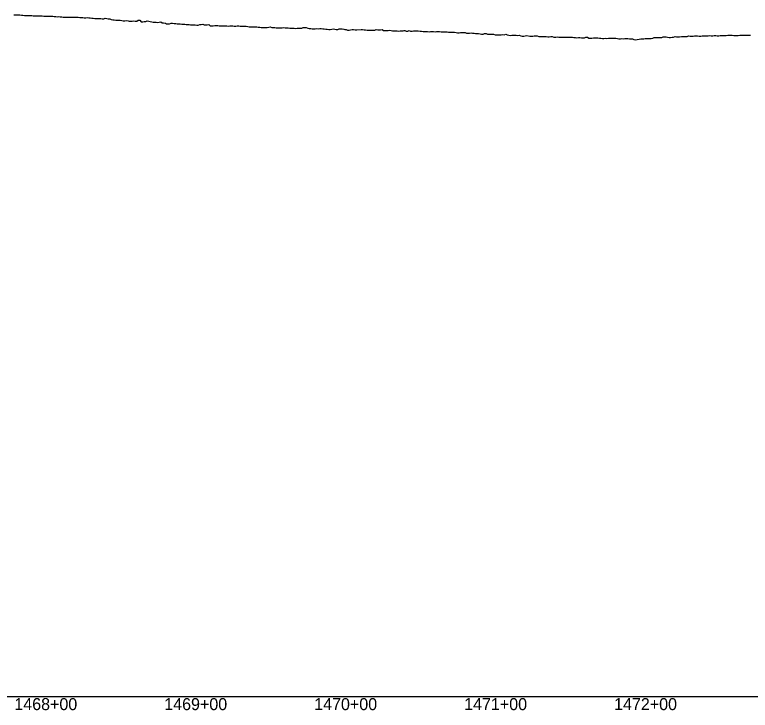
# Model space of a CAD drawing. Extents: x -3793 to 50787, y -1075 to 6138.
# Drawn here: x 34158.7 to 34649.2, y 990.9 to 1455 of the extents above; entities that cross this region are included whole.
import ezdxf

# ---------------------------------------------------------------- set-up
doc = ezdxf.new("R2010")
doc.units = 0
for name, color, linetype in [('RD_DDB_Profile_EX', 7, 'Continuous'), ('RD_DDB_StaTX', 7, 'Continuous'), ('RD_GPK_Profile_Cell', 7, 'Continuous')]:
    doc.layers.add(name, color=color, linetype=linetype)

msp = doc.modelspace()

# ---------------------------------------------------------------- linework, layer by layer
at = {"layer": 'RD_DDB_Profile_EX'}
for points in [[(34158.089552, 1454.92053), (34159.07989, 1454.87333), (34160.079882, 1454.911675), (34161.079874, 1454.95004), (34162.078945, 1454.81324), (34163.079056, 1454.55282), (34164.07905, 1454.597655), (34165.079045, 1454.508055), (34166.07701, 1454.4104), (34167.07712, 1454.41613), (34168.077118, 1454.454855), (34169.07621, 1454.446225), (34170.07621, 1454.42426), (34171.076209, 1454.28498), (34172.075414, 1454.2824), (34173.075415, 1454.248315), (34174.075417, 1454.18207), (34175.075419, 1454.271205), (34176.074625, 1454.263505), (34177.074628, 1454.1239), (34178.074631, 1454.073745), (34179.073733, 1454.015755), (34180.073842, 1453.991835), (34181.073848, 1454.03131), (34182.073853, 1454.015625), (34183.072958, 1454.057815), (34184.072965, 1454.01277), (34185.072172, 1453.82037), (34186.071277, 1453.68226), (34187.069473, 1453.630875), (34188.068576, 1453.66362), (34189.067772, 1453.61553), (34190.066873, 1453.42149), (34191.065974, 1453.4094), (34192.065076, 1453.40199), (34193.063337, 1453.350565), (34194.062435, 1453.351585), (34195.061533, 1453.336385), (34196.060631, 1453.387405), (34197.059729, 1453.388255), (34198.057964, 1453.28608), (34199.057059, 1453.34368), (34200.056153, 1453.31921), (34201.055247, 1453.309455), (34202.05441, 1453.160245), (34203.052614, 1453.107965), (34204.051767, 1452.976885), (34205.050916, 1452.9085), (34206.050001, 1452.890745), (34207.039704, 1452.982505), (34208.038828, 1452.938425), (34209.036954, 1452.790795), (34210.036068, 1452.6879), (34211.034692, 1452.53743), (34212.033816, 1452.436775), (34213.032889, 1452.47676), (34214.03101, 1452.32923), (34215.030121, 1452.322025), (34216.029229, 1452.31131), (34217.028333, 1452.260425), (34218.027433, 1452.305865), (34219.025511, 1452.5908), (34220.024601, 1452.37966), (34221.023657, 1452.28345), (34222.022741, 1452.283985), (34223.021822, 1451.74514), (34224.020898, 1451.54417), (34225.018928, 1451.487115), (34226.017993, 1451.382805), (34227.017055, 1451.330205), (34228.016098, 1451.372575), (34229.015153, 1451.22082), (34230.01314, 1451.065995), (34231.012184, 1450.962795), (34232.011224, 1450.95871), (34233.010261, 1451.0547), (34234.257573, 1450.850485), (34235.010263, 1450.557785), (34236.011246, 1450.612415), (34237.012232, 1450.615675), (34238.01321, 1450.81695), (34239.014186, 1450.72107), (34240.015169, 1450.676855), (34241.017106, 1451.227365), (34242.018071, 1451.281225), (34243.009219, 1450.298155), (34244.010195, 1450.297345), (34245.011187, 1450.35047), (34246.011189, 1450.40214), (34247.010219, 1450.830285), (34248.009262, 1450.63213), (34249.008284, 1450.48081), (34250.008286, 1450.2841), (34251.007316, 1450.07453), (34252.00633, 1450.023285), (34253.00534, 1449.874915), (34254.004354, 1449.771295), (34255.003355, 1449.965175), (34256.003357, 1450.16358), (34257.002358, 1449.560635), (34258.001351, 1449.505855)], [(34258.001351, 1449.505855), (34259.173674, 1449.40457), (34260.001167, 1448.953355), (34261.001281, 1448.95374), (34262.002489, 1448.958175), (34263.003692, 1449.26047), (34264.004891, 1449.313685), (34265.006097, 1449.118695), (34266.007289, 1449.07071), (34267.007416, 1448.969135), (34268.008606, 1448.873715), (34269.009809, 1448.827135), (34270.010993, 1448.728705), (34271.012194, 1448.63292), (34272.013371, 1448.53726), (34273.064954, 1448.4941), (34274.039694, 1448.40109), (34275.009409, 1448.356885), (34275.974137, 1448.1683), (34277.018247, 1448.11147), (34278.018361, 1448.15867), (34279.019558, 1448.11418), (34280.020717, 1448.068055), (34281.021912, 1448.02205), (34282.023106, 1448.36274), (34283.024258, 1448.361915), (34284.024414, 1448.55216), (34285.025563, 1448.26937), (34286.026756, 1448.17486), (34287.027898, 1448.1781), (34288.029088, 1448.3719), (34289.029202, 1447.46528), (34290.030392, 1447.562555), (34291.031526, 1447.616815), (34292.032714, 1447.7632), (34293.033842, 1447.81157), (34294.035028, 1447.671315), (34295.035141, 1447.577315), (34296.036327, 1447.53467), (34297.037447, 1447.476525), (34298.038631, 1447.48058), (34299.039744, 1447.49094), (34300.040926, 1447.488435), (34301.041039, 1447.388645), (34302.04222, 1447.43573), (34303.043326, 1447.49647), (34304.043515, 1447.45412), (34305.044618, 1447.25807), (34306.044809, 1447.204895), (34307.04591, 1447.486065), (34308.046104, 1447.621335), (34309.047203, 1447.351445), (34310.047399, 1447.29803), (34311.048495, 1447.33954), (34312.048693, 1447.39398), (34313.049787, 1447.380895), (34314.049988, 1447.097715), (34315.05108, 1446.967765), (34316.051282, 1446.964075), (34317.052372, 1446.87191), (34318.052577, 1446.826745), (34319.053758, 1446.871975), (34320.053871, 1446.858925), (34321.055053, 1446.712485), (34322.055166, 1446.54459), (34323.056249, 1446.38895), (34324.056362, 1446.39377), (34325.057341, 1446.437785), (34326.057454, 1446.433285), (34327.058426, 1446.47208), (34328.058538, 1446.69355), (34329.059503, 1446.82162), (34330.059616, 1446.420445), (34331.060574, 1446.38311), (34332.060582, 1446.328015), (34333.061637, 1446.236205), (34334.060637, 1446.23101), (34335.061669, 1446.28415), (34336.061675, 1446.27888), (34337.062702, 1446.27672), (34338.062707, 1446.30579), (34339.063729, 1446.26366), (34340.063732, 1446.263515), (34341.064748, 1446.082255), (34342.06475, 1446.07138), (34343.065652, 1446.07923), (34344.065762, 1445.9957), (34345.066657, 1445.8984), (34346.066767, 1445.848575), (34347.067656, 1445.97889), (34348.067766, 1446.06226), (34349.068649, 1445.97574), (34350.068758, 1446.014545), (34351.069636, 1446.40345), (34352.069745, 1446.503535), (34353.070616, 1446.314075), (34354.070725, 1446.06659), (34355.07159, 1445.750665), (34356.071582, 1445.694575), (34357.072558, 1445.565225), (34358.072549, 1445.565015)], [(34358.072549, 1445.565015), (34359.07352, 1445.611905), (34360.074368, 1445.66438), (34361.074476, 1445.620675), (34362.075319, 1445.654605), (34363.075427, 1445.69235), (34364.076263, 1445.550785), (34365.076371, 1445.588375), (34366.077202, 1445.31585), (34367.077187, 1445.271975), (34368.078135, 1445.13761), (34369.078119, 1445.17454), (34370.079063, 1445.394845), (34371.079046, 1445.507625), (34372.079985, 1445.22985), (34373.079966, 1445.10586), (34374.080901, 1445.158925), (34375.080882, 1445.455605), (34376.081812, 1445.494605), (34377.081792, 1445.487705), (34378.094939, 1445.26026), (34378.800898, 1445.18703), (34379.665484, 1444.973975), (34380.665539, 1444.73101), (34381.665579, 1444.734185), (34382.665631, 1444.884855), (34383.665685, 1445.10028), (34384.665725, 1445.09603), (34385.665778, 1444.92479), (34386.808537, 1444.856885), (34389.665965, 1445.05941), (34390.666017, 1445.009895), (34391.666057, 1444.798695), (34392.666112, 1444.89153), (34393.666164, 1444.59344), (34394.666204, 1444.54462), (34395.814873, 1444.610065), (34396.666296, 1444.697705), (34397.666351, 1444.690345), (34398.816985, 1444.698445), (34399.666443, 1444.99771), (34400.818951, 1444.855805), (34401.666536, 1444.773235), (34402.66659, 1444.89256), (34403.821063, 1444.985295), (34404.666683, 1444.48065), (34405.666737, 1444.404215), (34406.666778, 1444.39929), (34407.658408, 1444.510475), (34408.656884, 1444.552725), (34409.656924, 1444.48122), (34410.656976, 1444.255715), (34411.657016, 1444.22426), (34412.657071, 1444.282485), (34413.657123, 1444.26548), (34414.657163, 1444.03474), (34415.657215, 1444.20276), (34416.657256, 1444.222505), (34417.65731, 1444.24787), (34418.492034, 1444.456655), (34418.823003, 1444.45704), (34419.657403, 1443.95916), (34420.824966, 1443.94313), (34421.657495, 1444.40278), (34422.65755, 1443.95433), (34423.827075, 1443.96351), (34424.657642, 1444.13205), (34425.657697, 1444.19075), (34426.657737, 1444.19328), (34427.657789, 1444.226635), (34429.062929, 1443.977935), (34430.062057, 1443.908605), (34431.061181, 1443.723745), (34432.060508, 1443.7136), (34433.059625, 1443.73686), (34434.058739, 1443.676235), (34435.058051, 1443.62451), (34436.058172, 1443.67466), (34437.057278, 1443.7142), (34438.056581, 1443.762505), (34439.055679, 1443.610345), (34440.054775, 1443.650115), (34441.054063, 1443.674395), (34442.05315, 1443.66454), (34443.052234, 1443.62845), (34444.051314, 1443.61084), (34445.050391, 1443.51672), (34446.049275, 1443.499095), (34447.048346, 1443.489705), (34448.047414, 1443.303), (34449.046478, 1443.223465), (34450.045356, 1443.26361), (34451.044415, 1443.296985), (34452.04347, 1443.252305), (34453.033941, 1443.12892), (34454.032975, 1442.92665), (34455.032919, 1442.912255), (34456.031951, 1443.03911), (34457.03098, 1442.994115), (34458.030005, 1443.07153), (34459.029026, 1443.142575)], [(34459.029026, 1443.142575), (34460.027872, 1442.694455), (34461.026887, 1442.605625), (34462.025899, 1442.69026), (34463.024907, 1442.862195), (34464.023911, 1442.7232), (34465.022749, 1442.53358), (34466.021747, 1442.393965), (34467.020741, 1442.379315), (34468.019732, 1442.42106), (34469.018563, 1442.16687), (34470.017547, 1441.987995), (34471.016528, 1442.02326), (34472.015505, 1442.37401), (34473.014478, 1442.371755), (34474.0133, 1441.91994), (34475.013425, 1441.87013), (34476.012392, 1441.86161), (34478.010314, 1441.93417), (34479.187148, 1441.521185), (34480.187255, 1441.46612), (34481.187361, 1441.511045), (34483.187474, 1441.605775), (34484.188425, 1441.771595), (34485.188532, 1441.63249), (34486.188638, 1442.039675), (34487.188744, 1441.459705), (34488.188749, 1441.32563), (34489.188855, 1441.147345), (34490.188961, 1441.192185), (34491.189068, 1441.410085), (34492.189174, 1441.383315), (34493.189178, 1441.304695), (34494.189284, 1441.17645), (34495.189391, 1441.21586), (34496.189497, 1440.948465), (34497.189501, 1440.630615), (34498.189607, 1440.659265), (34499.189713, 1440.955435), (34500.189718, 1441.083645), (34502.18993, 1440.71644), (34503.189934, 1440.700025), (34504.19004, 1440.63938), (34505.190146, 1440.784135), (34506.19015, 1440.84479), (34507.190256, 1440.83955), (34508.190261, 1440.482665), (34509.190366, 1440.377455), (34510.190472, 1440.455975), (34511.190476, 1440.411205), (34512.190582, 1440.366815), (34513.18166, 1440.36117), (34514.181767, 1440.272195), (34515.181873, 1440.24527), (34516.182719, 1440.503965), (34517.182825, 1440.415105), (34518.182827, 1440.06994), (34518.65457, 1440.024005), (34519.653531, 1440.06326), (34520.653586, 1440.1025), (34521.653642, 1439.940595), (34522.653713, 1439.89417), (34523.653769, 1439.943995), (34524.653824, 1439.89417), (34525.653878, 1439.872745), (34526.653935, 1439.877985), (34527.65399, 1439.928145), (34528.654062, 1440.025375), (34529.654116, 1439.98617), (34530.654171, 1439.881015), (34531.654227, 1439.830855), (34532.654282, 1439.752315), (34533.654354, 1439.61485), (34534.654409, 1439.64931), (34535.654463, 1439.63899), (34536.65452, 1439.53883), (34537.654574, 1439.589), (34538.654629, 1439.56815), (34539.654701, 1439.968935), (34540.654756, 1439.98975), (34541.654812, 1439.35686), (34542.654867, 1439.301875), (34543.654921, 1439.341695), (34544.654978, 1439.55012), (34545.655048, 1439.45307), (34546.655104, 1439.50804), (34547.655159, 1439.56329), (34548.655214, 1439.3543), (34549.65527, 1439.249025), (34550.655324, 1439.169645), (34551.655397, 1439.140945), (34552.655451, 1439.191125), (34553.655506, 1439.116475), (34554.655562, 1439.206235), (34555.655617, 1439.19636), (34556.655673, 1439.2462), (34557.655743, 1439.28835), (34558.655798, 1439.203415), (34559.655854, 1439.308205), (34560.655909, 1438.988175), (34561.655965, 1438.92311)], [(34561.655965, 1438.92311), (34562.656036, 1438.960005), (34563.65609, 1438.969985), (34564.656146, 1438.89912), (34565.656201, 1439.08469), (34566.656256, 1439.084915), (34567.656312, 1439.01028), (34568.656382, 1438.89562), (34569.656438, 1438.819495), (34570.656493, 1438.784205), (34571.656548, 1438.40859), (34572.703854, 1438.28581), (34576.352599, 1438.89549), (34577.228106, 1438.91909), (34578.228954, 1438.937955), (34579.229168, 1439.02793), (34580.230014, 1439.12667), (34581.230858, 1439.142075), (34582.231074, 1439.15422), (34583.231916, 1439.17015), (34584.232849, 1439.302115), (34585.232975, 1439.700135), (34586.233812, 1439.709595), (34587.234743, 1439.75563), (34588.234869, 1439.685995), (34589.235702, 1439.734525), (34589.75821, 1439.763285), (34590.236658, 1439.7774), (34591.237541, 1440.094425), (34592.132656, 1440.238245), (34593.132991, 1440.23301), (34594.13408, 1439.994295), (34595.134289, 1439.764115), (34596.135505, 1439.76319), (34597.135713, 1439.900875), (34598.136053, 1439.865175), (34599.137138, 1440.47751), (34600.137346, 1440.224355), (34601.137689, 1440.10872), (34602.138771, 1440.09319), (34603.282319, 1440.31074), (34604.140253, 1440.32847), (34605.140527, 1440.422435), (34606.140802, 1440.386995), (34607.142085, 1440.364105), (34608.142359, 1440.8019), (34609.143499, 1440.66933), (34610.143916, 1440.620445), (34611.144191, 1440.67823), (34612.145328, 1440.89563), (34613.145748, 1440.89663), (34614.146023, 1440.761755), (34615.147305, 1440.630195), (34616.14758, 1440.73085), (34617.148734, 1440.826845), (34618.149226, 1440.855585), (34619.149568, 1440.94126), (34620.150763, 1440.909555), (34621.151258, 1440.953085), (34622.152451, 1440.998435), (34623.152791, 1440.95693), (34624.15329, 1440.95028), (34625.154479, 1440.98746), (34626.15482, 1441.030185), (34627.156167, 1440.941345), (34628.156508, 1440.900075), (34629.156848, 1440.992675), (34630.330538, 1441.070995), (34631.158592, 1441.038465), (34632.159165, 1441.022715), (34633.160413, 1441.100875), (34634.160821, 1441.284575), (34635.162235, 1441.19555), (34636.162471, 1441.27881), (34637.162706, 1441.254655), (34638.163943, 1441.174245), (34639.164176, 1441.174565), (34640.165232, 1441.18542), (34641.165462, 1441.177015), (34642.165866, 1441.34268), (34643.166913, 1441.33563), (34644.364844, 1441.31864), (34645.365056, 1441.25453), (34646.365853, 1441.265825), (34647.366063, 1441.27523), (34648.366273, 1441.366615), (34649.366958, 1441.36864)]]:
    msp.add_lwpolyline(points, dxfattribs=at)
at = {"layer": 'RD_GPK_Profile_Cell'}
msp.add_line((1000, 1000), (46600, 1000), dxfattribs=at)

# ---------------------------------------------------------------- texts
at = {"layer": 'RD_DDB_StaTX'}
for s, p in [('1468+00', (34158.415471, 991)), ('1469+00', (34258.415471, 991)), ('1470+00', (34358.415471, 991)), ('1471+00', (34458.415471, 991)), ('1472+00', (34558.415471, 991))]:
    msp.add_text(s, height=8, dxfattribs=at).set_placement(p)

doc.saveas('drawing.dxf')
